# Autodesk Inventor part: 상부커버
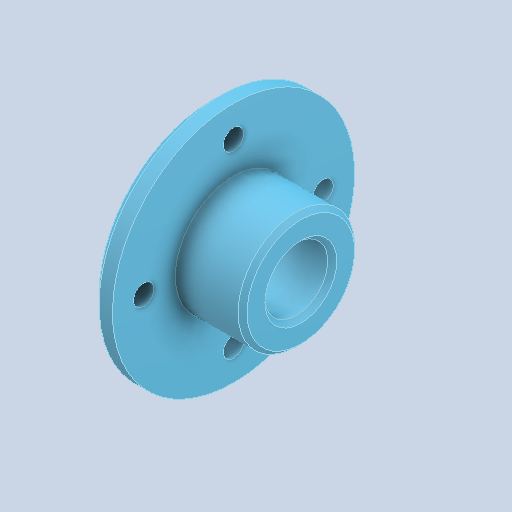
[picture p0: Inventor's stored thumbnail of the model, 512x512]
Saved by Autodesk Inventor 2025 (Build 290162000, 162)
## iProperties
Created: 2024-07
Part Number: 상부커버
Material: 알루미늄 6061
Document SubType Name: Modeling
Designer: samsung
Density: 2.71 g/cm^3
Appearance: 기본값
Author: jhkim
Sending System: Autodesk Inventor 2025
Preprocessor: ST-DEVELOPER v20
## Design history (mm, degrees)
feature "솔리드1"
node "솔리드2"
